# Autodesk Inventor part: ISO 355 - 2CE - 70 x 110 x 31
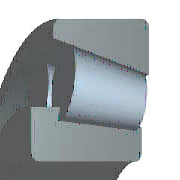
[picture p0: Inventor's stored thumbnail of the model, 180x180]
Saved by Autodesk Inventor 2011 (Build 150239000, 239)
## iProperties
IsCustomPart: 0
Created: 2009-02
Part Number: ISO 355 - 2CE - 70 x 110 x 31
Material: Steel, Mild
Description: Metric Tapered Roller Bearings
Document SubType Name: Modeling
Standard: ISO 355
Designer: 904Chiaki
Standard Revision: First edition 1977-05-01
Standards Organization: ISO
Language: en-US
Size Designation: 2CE - 70 x 110 x 31
Categories: <MemberInstance><Categories><Category DisplayName="Shaft Parts" InternalName="7f7aeb1f-a693-4053-b835-cee3144e0d98" Mnemonic="SHFT"><Category DisplayName="Beari
Density: 1 g/cm^3
Author: 904Chiaki
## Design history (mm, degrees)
revolve "Body" stored, may be unused: angle "d50" = 90 deg
revolve "Roller" stored, may be unused: angle "d53" = 90 deg
pattern_circular "Rollers" dims angle "d19" = 360 deg
body "Solid1"
sketch "Sketch"
  geometry: L1 (8.645, 46.842)-(9.131, 51.662); L2 (5.5, 52.352)-(31, 47.511); L3 (28.171, 48.048)-(27.855, 44.908); L4 (8.645, 46.842)-(27.855, 44.908); L5 (8.645, 46.842)-(8.16, 42.022); L6 (8.16, 42.022)-(27.538, 41.768); L7 (27.538, 41.768)-(27.855, 44.908); L8 (0, 0)-(0, 35); L9 (0, 0)-(31, 0); L10 (27.588, 42.264)-(31, 42.264); L11 (31, 42.264)-(31, 35); L12 (31, 35)-(0, 35); L13 (0, 44.005)-(8.36, 44.005); L14 (0, 44.005)-(0, 35); L15 (31, 47.511)-(31, 55); L16 (31, 55)-(5.5, 55); L17 (5.5, 55)-(5.5, 52.352); L18 (18.25, 45.875)-(18.651, 49.855); L19 (5.5, 52.352)-(31, 47.511); L20 (5.5, 52.352)-(5.5, 52.352); L21 (31, 47.511)-(31, 47.511); L22 (18.651, 49.855)-(18.651, 49.855); L23 (27.539, 41.769)-(8.16, 42.023)
  constraints: 46 end point, 10 parallel, 9 point on line, 5 perpendicular, 2 collinear, 1 midpoint, 1 vertical, 3 other
  dimensions: "d1" = 19.38 distance of L5.end L6.end (= 0.76 x KAB); "d2" = 25.5 distance of L15.end L16.end (= KAB); "d3" = 70 diameter of L12 L9 (= WD); "d5" = 110 diameter of L16 L9 (= BD); "d7" = 95.021 diameter of L2.end L9 (= BBB); "d8" = 31 distance of L11.end L8.end (= KB1); "d9" = 31 distance between parallel lines of L14 L15 (= KB); "d10" = 10.75 deg angle of L2 L13 (= BBA); "d11" = 5 deg angle of L2 L4; "d12" = 4 distance of L18.end L18.start (= -0.1 x WD + 0.1 x BD); "d13" = 12.75 distance from line of L15 L18.start (= 0.5 x KAB); "d14" = 1.98244 distance from line of L13 L5.end (computed from BBB, KAB, BBA, BD, WD); "d15" = 0.49561 distance from line of L10 L6.end (computed from BBB, KAB, BBA, BD, WD); "d27" = 4.0001 distance of L18.start L22.end (computed from d12); "d66" = 0.001 distance between parallel lines of L6 L23
fillet "Fillet1" dims "d16" = 1.5 (= KR3S), "d17" = 1.5 (= KR1S)
other parameters: "WD" = 70 [user parameter; used in 6 equation terms], "BD" = 110 [user parameter; used in 6 equation terms], "KB" = 31 [user parameter; used in 1 equation term], "KB1" = 31 [user parameter; used in 1 equation term], "KR1S" = 1.5 [user parameter; used in 1 equation term], "KR3S" = 1.5 [user parameter; used in 1 equation term], "BBA" = 10.75 deg [user parameter; used in 4 equation terms], "BBB" = 95.021 [user parameter; used in 4 equation terms], "KAB" = 25.5 [user parameter; used in 6 equation terms], "d22" = 0, "d23" = 0, "d24" = 0, "d25" = 0, "d26" = 0, "WR" = 35 (= 0.5 x WD) [user parameter], "BC0" = 1.08e+08 [user parameter], "BC" = 1.1e+08 [user parameter], "BR" = 55 (= 0.5 x BD) [user parameter]
